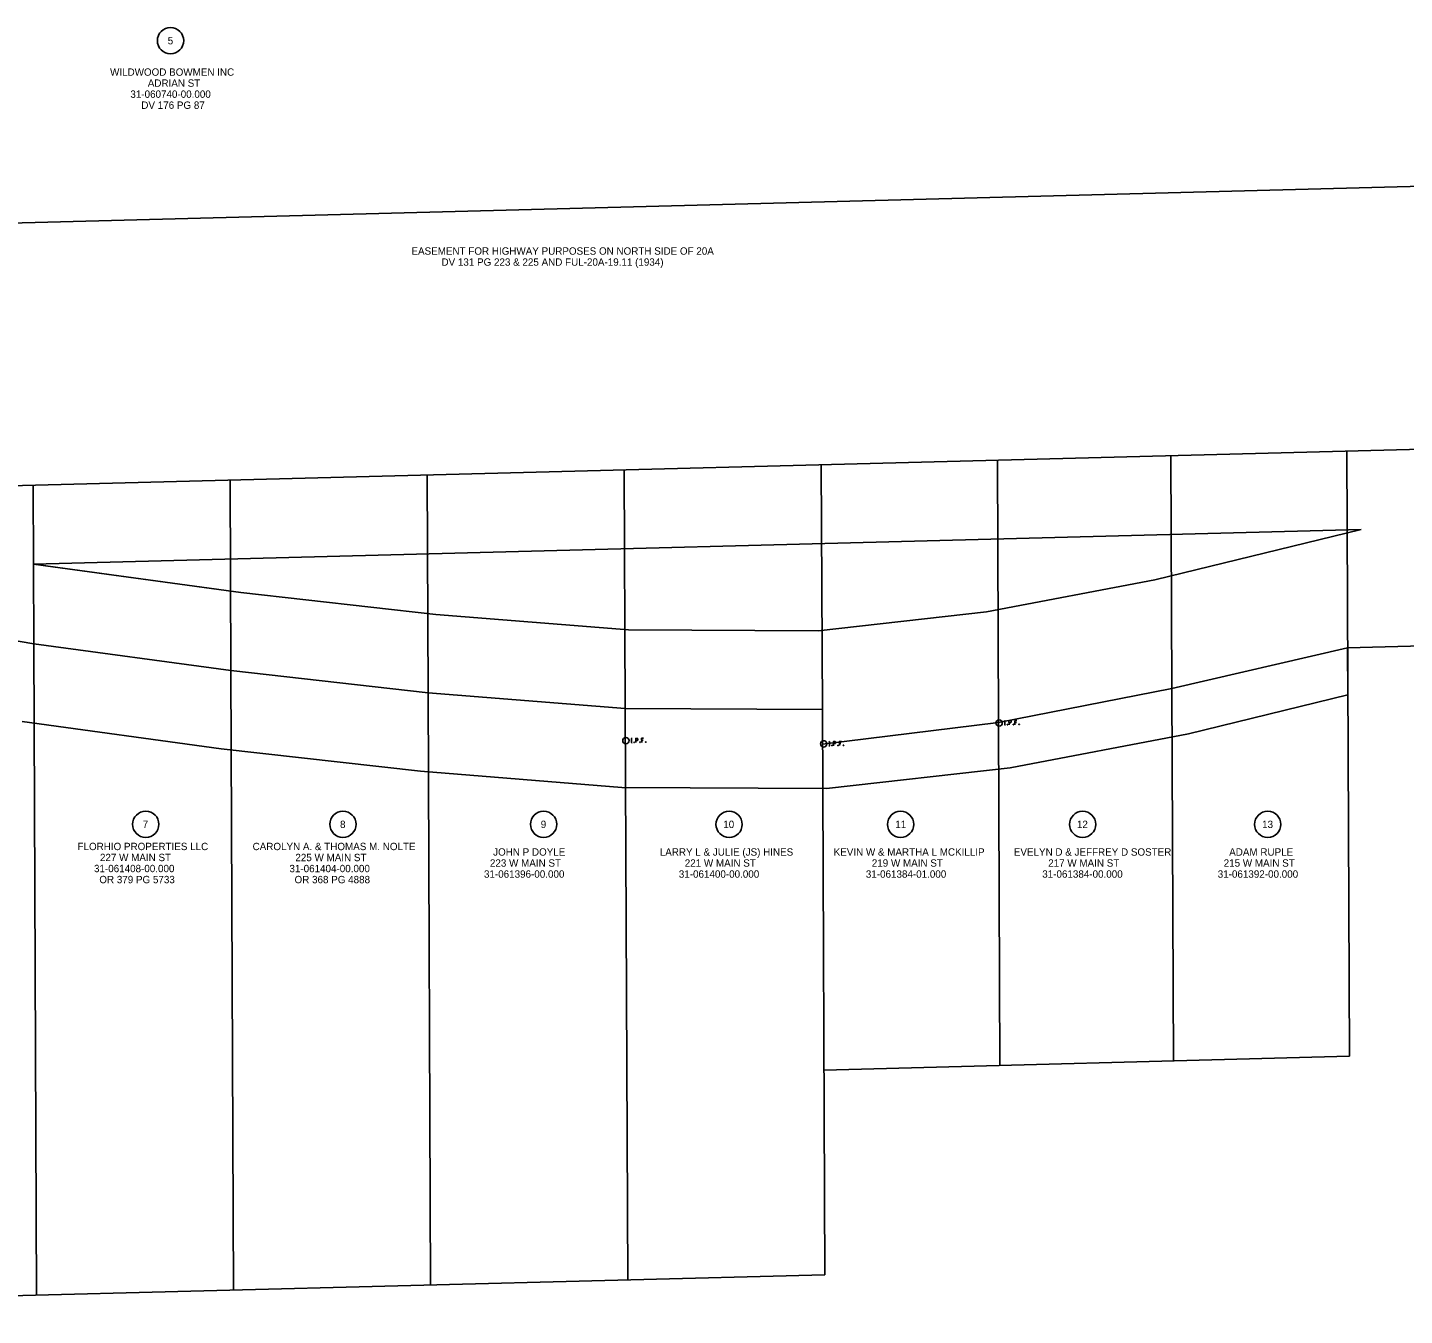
# Model space of a CAD drawing. Extents: x 200073 to 202746, y 352381 to 357578.
# Drawn here: x 200912 to 201436, y 354643 to 355134 of the extents above; entities that cross this region are included whole.
import ezdxf

# ---------------------------------------------------------------- set-up
doc = ezdxf.new("R2010")
doc.units = 0
for name, color, linetype in [('_CIVIL_CONSTRUCTION', 7, 'Continuous'), ('RW_X_CL_100_Bearings', 7, 'Continuous'), ('RW_X_CL_100_Cardinal_Points', 7, 'Continuous'), ('RW_X_CL_100_Stations', 7, 'Continuous'), ('RW_X_CL_500_Bearings', 7, 'Continuous'), ('RW_X_CL_500_Cardinal_Points', 7, 'Continuous'), ('SC_Scratch1', 7, 'Continuous')]:
    doc.layers.add(name, color=color, linetype=linetype)

msp = doc.modelspace()

# ---------------------------------------------------------------- linework, layer by layer
at = {"layer": '_CIVIL_CONSTRUCTION'}
msp.add_line((200083.32, 354937.76), (202745.29, 355007.24), dxfattribs=at)
at = {"layer": 'RW_X_CL_100_Bearings'}
for p, q in [((201281.24, 354869.21), (201280.81, 354969.01)), ((201346.79, 354970.74), (201347.17, 354882.08)), ((201413.77, 354972.48), (201414.76, 354742.08)), ((201138.85, 354965.31), (201139.24, 354874.46)), ((201213.83, 354967.27), (201214.23, 354874.06)), ((200913.92, 354959.44), (200914.18, 354899.14)), ((200988.9, 354961.4), (200989.21, 354888.89)), ((201063.87, 354963.35), (201064.23, 354880.45)), ((200839.14, 354911.48), (200914.18, 354899.14)), ((200914.18, 354899.14), (200915.24, 354651.13)), ((200914.18, 354899.14), (200989.21, 354888.89)), ((201347.17, 354882.08), (201414.09, 354897.58)), ((200989.21, 354888.89), (200990.22, 354653.08)), ((200989.21, 354888.89), (201064.23, 354880.45)), ((201064.23, 354880.45), (201065.19, 354655.04)), ((201064.23, 354880.45), (201139.24, 354874.46)), ((201347.17, 354882.08), (201281.24, 354869.21)), ((201347.17, 354882.08), (201347.78, 354740.33)), ((201139.24, 354874.46), (201140.17, 354657)), ((201139.24, 354874.46), (201214.23, 354874.06)), ((201214.23, 354874.06), (201215.15, 354658.95)), ((201281.24, 354869.21), (201214.29, 354860.86)), ((201281.8, 354738.61), (201281.24, 354869.21)), ((201414.76, 354742.08), (201214.82, 354736.86)), ((201215.15, 354658.95), (200620.33, 354643.43))]:
    msp.add_line(p, q, dxfattribs=at)
at = {"layer": 'RW_X_CL_100_Cardinal_Points'}
for p, q in [((201414.09, 354897.58), (201637.62, 354903.42)), ((201414.17, 354879.62), (201414.09, 354897.58))]:
    msp.add_line(p, q, dxfattribs=at)
at = {"layer": 'RW_X_CL_100_Stations'}
for centre in [(200966.22, 355128.69), (200956.8, 354830.39), (201031.82, 354830.39), (201108.17, 354830.39), (201178.75, 354830.38), (201244, 354830.38), (201313.25, 354830.38), (201383.69, 354830.38)]:
    msp.add_circle(centre, 5, dxfattribs=at)
at = {"layer": 'RW_X_CL_500_Bearings'}
for p, q in [((200731.62, 355054.72), (201543.51, 355075.91)), ((200914.06, 354929.43), (201419.25, 354942.62)), ((201340.76, 354923.48), (201419.24, 354942.62)), ((201340.76, 354923.48), (201419.24, 354942.62)), ((200914.06, 354929.43), (200992.91, 354918.67)), ((200914.74, 354929.45), (200918.64, 354928.81)), ((200918.64, 354928.81), (200992.91, 354918.67)), ((201276.7, 354911.3), (201340.76, 354923.48)), ((201276.7, 354911.3), (201340.76, 354923.48)), ((200992.91, 354918.67), (201067.1, 354910.32)), ((200992.91, 354918.67), (201067.1, 354910.32)), ((201212.62, 354904.07), (201276.7, 354911.3)), ((201212.62, 354904.07), (201276.7, 354911.3)), ((201067.1, 354910.32), (201140.52, 354904.45)), ((201067.1, 354910.32), (201140.52, 354904.45)), ((201140.52, 354904.45), (201212.62, 354904.07)), ((201140.52, 354904.45), (201212.62, 354904.07)), ((201353.48, 354864.82), (201414.17, 354879.62)), ((200909.71, 354869.47), (200985.5, 354859.12)), ((201285.68, 354851.93), (201353.48, 354864.82)), ((200985.5, 354859.12), (201061.36, 354850.58)), ((201061.36, 354850.58), (201137.97, 354844.46)), ((201215.84, 354844.05), (201285.68, 354851.93)), ((201137.97, 354844.46), (201215.84, 354844.05))]:
    msp.add_line(p, q, dxfattribs=at)
at = {"layer": 'SC_Scratch1'}
for points in [[(201283.48, 354869.82), (201283.84, 354869.83)], [(201283.69, 354868.23), (201283.66, 354869.83)], [(201285.26, 354868.26), (201285.23, 354869.86), (201285.75, 354869.87), (201285.81, 354869.85), (201285.89, 354869.83), (201285.92, 354869.81), (201285.95, 354869.78), (201286, 354869.72), (201286.03, 354869.66), (201286.06, 354869.56), (201286.06, 354869.41), (201286.05, 354869.35), (201286.03, 354869.28), (201285.99, 354869.19), (201285.94, 354869.15), (201285.91, 354869.13), (201285.86, 354869.1), (201285.77, 354869.08), (201285.24, 354869.07)], [(201288.23, 354869.91), (201287.47, 354869.9), (201287.5, 354868.3)], [(201287.49, 354869.12), (201288.03, 354869.13)], [(201283.51, 354868.22), (201283.87, 354868.23)], [(201284.65, 354868.46), (201284.7, 354868.46), (201284.73, 354868.44), (201284.77, 354868.39), (201284.77, 354868.32), (201284.74, 354868.27), (201284.71, 354868.25), (201284.65, 354868.24), (201284.62, 354868.27), (201284.58, 354868.32), (201284.58, 354868.38), (201284.61, 354868.43), (201284.65, 354868.46)], [(201286.89, 354868.5), (201286.95, 354868.5), (201286.98, 354868.48), (201287.02, 354868.43), (201287.02, 354868.36), (201286.99, 354868.31), (201286.95, 354868.29), (201286.9, 354868.29), (201286.86, 354868.31), (201286.83, 354868.36), (201286.83, 354868.42), (201286.86, 354868.48), (201286.89, 354868.5)], [(201289.04, 354868.54), (201289.1, 354868.54), (201289.13, 354868.52), (201289.17, 354868.47), (201289.17, 354868.41), (201289.14, 354868.35), (201289.1, 354868.33), (201289.05, 354868.33), (201289.01, 354868.35), (201288.98, 354868.4), (201288.98, 354868.47), (201289.01, 354868.52), (201289.04, 354868.54)], [(201141.46, 354863.07), (201141.81, 354863.08)], [(201141.49, 354861.47), (201141.84, 354861.48)], [(201141.67, 354861.48), (201141.64, 354863.08)], [(201142.62, 354861.71), (201142.68, 354861.71), (201142.71, 354861.69), (201142.74, 354861.64), (201142.74, 354861.57), (201142.71, 354861.52), (201142.68, 354861.5), (201142.62, 354861.5), (201142.59, 354861.52), (201142.56, 354861.57), (201142.56, 354861.63), (201142.59, 354861.68), (201142.62, 354861.71)], [(201143.23, 354861.51), (201143.2, 354863.11), (201143.73, 354863.12), (201143.78, 354863.1), (201143.86, 354863.08), (201143.9, 354863.06), (201143.93, 354863.03), (201143.97, 354862.97), (201144.01, 354862.91), (201144.03, 354862.81), (201144.04, 354862.66), (201144.03, 354862.61), (201144.01, 354862.53), (201143.96, 354862.44), (201143.92, 354862.4), (201143.89, 354862.38), (201143.83, 354862.35), (201143.74, 354862.34), (201143.22, 354862.33)], [(201144.87, 354861.75), (201144.92, 354861.75), (201144.96, 354861.73), (201144.99, 354861.68), (201144.99, 354861.62), (201144.96, 354861.56), (201144.93, 354861.54), (201144.87, 354861.54), (201144.84, 354861.56), (201144.81, 354861.61), (201144.8, 354861.68), (201144.84, 354861.73), (201144.87, 354861.75)], [(201146.21, 354863.16), (201145.45, 354863.15), (201145.48, 354861.55)], [(201145.46, 354862.37), (201146, 354862.38)], [(201147.02, 354861.79), (201147.07, 354861.79), (201147.11, 354861.77), (201147.14, 354861.72), (201147.14, 354861.66), (201147.11, 354861.61), (201147.08, 354861.58), (201147.02, 354861.58), (201146.99, 354861.6), (201146.95, 354861.65), (201146.95, 354861.72), (201146.99, 354861.77), (201147.02, 354861.79)], [(201216.71, 354861.85), (201217.06, 354861.86)], [(201216.74, 354860.25), (201217.09, 354860.26)], [(201216.91, 354860.26), (201216.88, 354861.86)], [(201217.87, 354860.49), (201217.92, 354860.49), (201217.96, 354860.47), (201217.99, 354860.42), (201217.99, 354860.35), (201217.96, 354860.3), (201217.93, 354860.28), (201217.87, 354860.28), (201217.84, 354860.3), (201217.81, 354860.35), (201217.8, 354860.41), (201217.84, 354860.46), (201217.87, 354860.49)], [(201218.48, 354860.29), (201218.45, 354861.89), (201218.98, 354861.9), (201219.03, 354861.88), (201219.11, 354861.86), (201219.15, 354861.84), (201219.18, 354861.81), (201219.22, 354861.75), (201219.26, 354861.69), (201219.28, 354861.59), (201219.28, 354861.44), (201219.27, 354861.39), (201219.25, 354861.31), (201219.21, 354861.22), (201219.17, 354861.18), (201219.14, 354861.16), (201219.08, 354861.13), (201218.99, 354861.12), (201218.46, 354861.11)], [(201220.12, 354860.53), (201220.17, 354860.53), (201220.21, 354860.51), (201220.24, 354860.46), (201220.24, 354860.4), (201220.21, 354860.34), (201220.18, 354860.32), (201220.12, 354860.32), (201220.09, 354860.34), (201220.05, 354860.39), (201220.05, 354860.46), (201220.09, 354860.51), (201220.12, 354860.53)], [(201221.46, 354861.94), (201220.7, 354861.93), (201220.73, 354860.33)], [(201220.71, 354861.15), (201221.25, 354861.16)], [(201222.27, 354860.57), (201222.32, 354860.57), (201222.36, 354860.55), (201222.39, 354860.5), (201222.39, 354860.44), (201222.36, 354860.39), (201222.33, 354860.36), (201222.27, 354860.36), (201222.24, 354860.38), (201222.2, 354860.43), (201222.2, 354860.5), (201222.23, 354860.55), (201222.27, 354860.57)]]:
    msp.add_lwpolyline(points, dxfattribs=at)
for centre in [(201281.49, 354868.98), (201139.46, 354862.24), (201214.71, 354861.02)]:
    msp.add_circle(centre, 1.2, dxfattribs=at)

# ---------------------------------------------------------------- texts
at = {"layer": 'RW_X_CL_100_Stations'}
for s, p in [('5', (200965.15, 355127.29)), ('WILDWOOD BOWMEN INC', (200943.22, 355115.34)), ('ADRIAN ST', (200957.57, 355111.14)), ('31-060740-00.000', (200950.94, 355106.94)), ('DV 176 PG 87', (200955.11, 355102.74))]:
    msp.add_text(s, height=2.8, dxfattribs=at).set_placement(p)
for s, p in [('7', (200955.62, 354828.99)), ('8', (201030.72, 354828.99)), ('9', (201107.08, 354828.99)), ('10', (201176.52, 354828.98)), ('11', (201241.97, 354828.98)), ('12', (201311.08, 354828.98)), ('13', (201381.54, 354828.98)), ('FLORHIO PROPERTIES LLC', (200930.83, 354820.57)), ('CAROLYN A. & THOMAS M. NOLTE', (200997.45, 354820.56)), ('227 W MAIN ST', (200939.37, 354816.37)), ('225 W MAIN ST', (201013.72, 354816.36)), ('223 W MAIN ST', (201087.74, 354814.26)), ('JOHN P DOYLE', (201088.96, 354818.46)), ('LARRY L & JULIE (JS) HINES', (201152.37, 354818.46)), ('221 W MAIN ST', (201161.87, 354814.26)), ('KEVIN W & MARTHA L MCKILLIP', (201218.53, 354818.46)), ('219 W MAIN ST', (201233.04, 354814.26)), ('EVELYN D & JEFFREY D SOSTER', (201287.08, 354818.46)), ('217 W MAIN ST', (201300.16, 354814.26)), ('215 W MAIN ST', (201366.92, 354814.26)), ('ADAM RUPLE', (201369.02, 354818.45)), ('31-061408-00.000', (200937.1, 354812.17)), ('31-061404-00.000', (201011.46, 354812.16)), ('31-061396-00.000', (201085.48, 354810.06)), ('31-061400-00.000', (201159.61, 354810.06)), ('31-061384-01.000', (201230.77, 354810.06)), ('31-061384-00.000', (201297.89, 354810.06)), ('31-061392-00.000', (201364.65, 354810.06)), ('OR 379 PG 5733', (200939.13, 354807.97)), ('OR 368 PG 4888', (201013.41, 354807.96))]:
    msp.add_text(s, height=2.8, rotation=359.9985, dxfattribs=at).set_placement(p)
at = {"layer": 'RW_X_CL_500_Cardinal_Points'}
for s, p in [('EASEMENT FOR HIGHWAY PURPOSES ON NORTH SIDE OF 20A', (201057.89, 355047.22)), ('DV 131 PG 223 & 225 AND FUL-20A-19.11 (1934)', (201069.31, 355043.02))]:
    msp.add_text(s, height=2.8, dxfattribs=at).set_placement(p)

doc.saveas('drawing.dxf')
